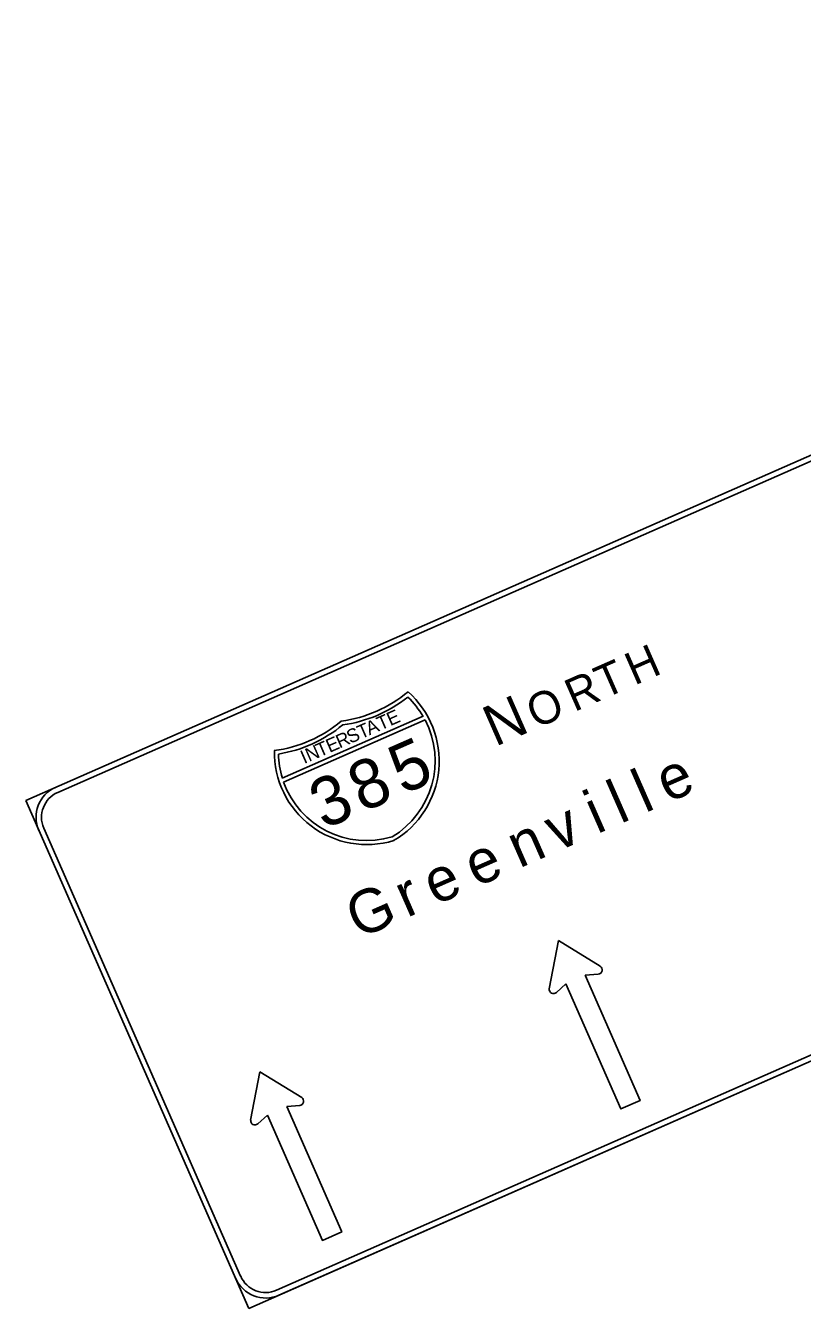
# Model space of a CAD drawing. Extents: x 1581789 to 1622364, y 1043167 to 1103486.
# Drawn here: x 1613077.3 to 1613172.5, y 1087379 to 1087536.3 of the extents above; entities that cross this region are included whole.
import ezdxf

# ---------------------------------------------------------------- set-up
doc = ezdxf.new("R2010")
doc.units = 0
doc.layers.add('RD_PD_PatLn2', color=7, linetype='Continuous')

msp = doc.modelspace()

# ---------------------------------------------------------------- linework, layer by layer
at = {"layer": 'RD_PD_PatLn2'}
for p, q in [((1613293.31, 1087536.26), (1613077.27, 1087441.27)), ((1613104.63, 1087379.02), (1613320.67, 1087474.01)), ((1613126, 1087451.6), (1613108.74, 1087444.01)), ((1613108.9, 1087443.53), (1613126.25, 1087451.16)), ((1613077.27, 1087441.27), (1613104.63, 1087379.02)), ((1613093.36, 1087404.65), (1613093.36, 1087404.65)), ((1613104.63, 1087379.02), (1613104.63, 1087379.02))]:
    msp.add_line(p, q, dxfattribs=at)
for points in [[(1613289.91, 1087534.04), (1613081.2, 1087442.27)], [(1613108.03, 1087381.24), (1613316.74, 1087473.01)], [(1613317.01, 1087472.4), (1613108.3, 1087380.63)], [(1613079.49, 1087437.88), (1613103.63, 1087382.95)], [(1613142.61, 1087424.12), (1613141.48, 1087418.19)], [(1613147.74, 1087420.95), (1613142.61, 1087424.12), (1613142.61, 1087424.12)], [(1613145.9, 1087419.85), (1613147.5, 1087420)], [(1613145.9, 1087419.85), (1613152.65, 1087404.5), (1613152.65, 1087404.5)], [(1613142.35, 1087417.73), (1613143.53, 1087418.81)], [(1613152.65, 1087404.5), (1613150.28, 1087403.46), (1613143.53, 1087418.81)], [(1613105.99, 1087408.02), (1613104.86, 1087402.09)], [(1613111.13, 1087404.85), (1613105.99, 1087408.02), (1613105.99, 1087408.02)], [(1613109.28, 1087403.75), (1613110.88, 1087403.9)], [(1613109.28, 1087403.75), (1613116.03, 1087388.4), (1613116.03, 1087388.4)], [(1613105.73, 1087401.63), (1613106.92, 1087402.71)], [(1613116.03, 1087388.4), (1613113.67, 1087387.36), (1613106.92, 1087402.71)]]:
    msp.add_lwpolyline(points, dxfattribs=at)
for centre, radius, start, end in [((1613113.88, 1087466.87), 16, 277.4759, 309.9913), ((1613113.91, 1087466.89), 16.5, 277.8477, 308.3302), ((1613116.65, 1087446.12), 11.33, 300.4899, 48.4867), ((1613116.65, 1087446.12), 10.83, 30.3347, 46.2453), ((1613105.68, 1087463.26), 16, 277.4759, 309.9913), ((1613116.66, 1087446.12), 10.83, 300.8022, 27.6981), ((1613105.64, 1087463.26), 16.5, 279.1369, 309.6194), ((1613119.1, 1087447.2), 11.33, 178.9804, 286.9773), ((1613119.1, 1087447.2), 10.83, 181.2219, 197.1323), ((1613082.54, 1087439.22), 4, 113.7337, 203.7334), ((1613119.1, 1087447.19), 10.83, 199.7691, 286.665), ((1613082.54, 1087439.22), 3.33, 113.7337, 203.7334), ((1613147.45, 1087420.52), 0.521, 275.1497, 55.942), ((1613142, 1087418.12), 0.521, 171.5251, 312.3175), ((1613110.83, 1087404.42), 0.521, 275.1497, 55.942), ((1613105.38, 1087402.02), 0.521, 171.5251, 312.3175), ((1613106.69, 1087384.29), 4, 203.7334, 293.7336), ((1613106.69, 1087384.29), 3.33, 203.7334, 293.7336)]:
    msp.add_arc(centre, radius, start, end, dxfattribs=at)

# ---------------------------------------------------------------- texts
for s, height, p in [('H', 4, (1613151.93, 1087455.35)), ('T', 4, (1613148.19, 1087453.7)), ('R', 4, (1613144.55, 1087452.1)), ('N', 5, (1613134.84, 1087447.83)), ('O', 4, (1613139.83, 1087450.03)), ('E', 1.67, (1613121.99, 1087450.38)), ('T', 1.67, (1613118.38, 1087448.79)), ('A', 1.67, (1613119.41, 1087449.24)), ('T', 1.67, (1613120.78, 1087449.84)), ('E', 1.67, (1613114.54, 1087447.1)), ('R', 1.67, (1613115.76, 1087447.64)), ('S', 1.67, (1613117.07, 1087448.21)), ('N', 1.67, (1613112.02, 1087445.99)), ('T', 1.67, (1613113.33, 1087446.57)), ('5', 6, (1613123.53, 1087441.95)), ('I', 1.67, (1613111.42, 1087445.73)), ('8', 6, (1613118.55, 1087439.76)), ('e', 5.33, (1613156.03, 1087440.95)), ('3', 6, (1613113.83, 1087437.69)), ('l', 5.33, (1613153.22, 1087439.71)), ('l', 5.33, (1613150.21, 1087438.39)), ('i', 5.33, (1613147.34, 1087437.13)), ('v', 5.33, (1613142.43, 1087434.97)), ('n', 5.33, (1613137.8, 1087432.93)), ('e', 5.33, (1613132.53, 1087430.61)), ('e', 5.33, (1613127.48, 1087428.39)), ('G', 5.33, (1613118.08, 1087424.26)), ('r', 5.33, (1613124.01, 1087426.87))]:
    msp.add_text(s, height=height, rotation=23.7335, dxfattribs=at).set_placement(p)

doc.saveas('drawing.dxf')
